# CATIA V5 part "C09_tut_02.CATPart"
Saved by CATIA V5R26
Part number: Part1
Bounding box of the stored display mesh (mm): x -258 to 0, y -74.587 to 74.587, z -81.796 to 81.796
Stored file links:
  D:\_Deepak\CATIA\CATIA V5 2015 Parts Files\Tutorial Files\Tutorials\c09_catia_v5_6r2015_tut\C09_tut_02.CATPart
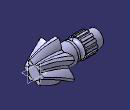
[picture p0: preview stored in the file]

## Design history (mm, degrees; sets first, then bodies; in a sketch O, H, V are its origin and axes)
Body1 (main body)
  Sketch1 on zx-plane, origin (0, 0, 0), H (-1, 0, 0), V (0, 0, 1)
    line L1 (0, 0) -> (258, 0)
    line L2 (258, 0) -> (258, -32.5)
    line L3 (0, 0) -> (0, -25)
    line L4 (0, -25) -> (95, -50)
    point P4 (95, -50)
    point P5 (95, -50)
    line L5 (95, -50) -> (95, -45)
    line L6 (95, -45) -> (100, -45)
    line L7 (100, -45) -> (100, -39)
    line L8 (100, -39) -> (146, -39)
    line L9 (258, -32.5) -> (226, -32.5)
    line L10 (226, -32.5) -> (226, -36)
    line L11 (226, -36) -> (178, -36)
    arc A1 centre (167, -36) radius 11 from (178, -36) to (156, -36) ccw
    point P13 (167, -36)
    line L12 (146, -39) -> (146, -38)
    line L13 (146, -38) -> (156, -38)
    line L14 (156, -38) -> (156, -36)
    point P16 (156, -36)
    point P17 (156, -36)
    axis line L15 (258, 0) -> (-34.5416, 0)
    length L1 = 258
    length L2 = 32.5
    length L3 = 25
    distance P4 L3 = 95
    length L5 = 5
    length L6 = 5
    distance L6 L1 = 45
    length L9 = 32
    length L10 = 3.5
    radius A1 = 11
    length L12 = 1
    length L13 = 10
    length L14 = 2
    distance L13 L1 = 38
    length L11 = 48
    horizontal: L1 H, L6 H, L8 H, L9 H, L11 H, L13 H, L15 H
    vertical: L2 V, L3 V, L5 V, L7 V, L10 V, L12 V, L14 V
    coincidence: P5 P4, P13 L11, P16 P17
  Shaft1: profile Sketch1, axis Sketch1.L15, angle 360
  Sketch2 on face of Shaft1 from Sketch1.L10, origin (-226, 0, 0), H (0, -1, 0), V (0, 0, 1)
    line L1 (-5, 40.6511) -> (5, 40.6511)
    line L2 (5, 40.6511) -> (5, 35.6511)
    line L3 (-5, 35.6511) -> (-5, 40.6511)
    point P3 (5, 35.6511)
    point P4 (-5, 35.6511)
    reference projected circle E1 centre (0, 0) radius 36 from edge [face of Shaft1 from Sketch1.L10 | face of Shaft1 from Sketch1.L11]
    reference projected circle E2 centre (0, 0) radius 36 from edge [face of Shaft1 from Sketch1.L10 | face of Shaft1 from Sketch1.L11]
    point P5 (0, 35.9986)
    point P6 (12.0414, 33.9264)
    arc A1 centre (0, 0) radius 36 from (5, 35.6511) to (-5, 35.6511) ccw
    length L3 = 5
    length L1 = 10
    distance L2 V = 5
    horizontal: L1 H
    vertical: L2 V, L3 V
    coincidence: P3 E1, P4 E2, P5 V
  Pad1: profile Sketch2, direction (1, 0, 0), length 48
  CircPattern1: of Pad1, instances 13, angular step 27.6923 {= 360.0*1 deg/CircPattern1.AngularNumber}, axis from face of Shaft1 from Sketch1.L9
  Plane1: type Offset, RefPlane face of Shaft1 from Sketch1.L2, Offset 163
  Sketch3 on Plane1, origin (-95, 0, 0), H (0, 1, 0), V (0, 0, 1)
    projected circle E1 centre (0, 0) radius 50 from edge [face of Shaft1 from Sketch1.L5 | face of Shaft1 from Sketch1.L4]
    projected arc E2 centre (0, 0) radius 50 from (20, 45.8258) to (-20, 45.8258) ccw from edge [face of Shaft1 from Sketch1.L5 | face of Shaft1 from Sketch1.L4]
    arc A1 centre (44.9551, 43.4104) radius 65 from (-20, 45.8258) to (-7.5, 81.7961) cw
    point P2 (-20, 45.8258)
    point P3 (-7.5, 81.7961)
    point P4 (20, 45.8258)
    point P5 (7.5, 81.7961)
    arc A2 centre (-44.9551, 43.4104) radius 65 from (20, 45.8258) to (7.5, 81.7961) ccw
    line L1 (-7.5, 81.7961) -> (7.5, 81.7961)
    radius A1 = 65
    length L1 = 15
    distance P2 P4 = 40
    coincidence: P2 E1
    symmetry: P2 P4 V, P3 P5 V, A1 A2 V
    horizontal: L1 H
  Plane2: type Offset, RefPlane face of Shaft1 from Sketch1.L2, Offset 210
  Sketch4 on Plane2, origin (-48, 0, 0), H (0, 1, 0), V (0, 0, 1)
    arc A1 centre (0, 0) radius 37.5 from (5.5935, 37.0805) to (-23.3843, 29.3159) ccw
    point P1 (5.5935, 37.0805)
    point P2 (-23.3843, 29.3159)
    arc A2 centre (-40.9945, 22.7216) radius 48.7506 from (5.5935, 37.0805) to (-10.4445, 60.7126) ccw
    point P3 (-10.4445, 60.7126)
    line L1 (-10.4445, 60.7126) -> (-21.3111, 57.8008)
    point P4 (-21.3111, 57.8008)
    arc A3 centre (24.1415, 40.1748) radius 48.7506 from (-21.3111, 57.8008) to (-23.3843, 29.3159) ccw
    reference projected circle E1 centre (0, 0) radius 25 from edge [face of Shaft1 from Sketch1.L4 | face of Shaft1 from Sketch1.L3]
    length L1 = 11.25
    radius A3 = 48.7506
    radius A1 = 37.5
    angle L1 H = 15
    radius A2 = 48.7506
    distance P1 V = 5.5935
    distance P2 V = 23.3843
    distance P3 V = 10.4445
    distance P4 H = 57.8008
    concentricity: A1 E1
  Sketch5 on face of Shaft1 from Sketch1.L3, origin (0, 0, 0), H (0, 1, 0), V (0, 0, 1)
    arc A1 centre (0, 0) radius 25 from (-2.7962, 24.8431) to (-20.1167, 14.8431) ccw
    arc A2 centre (-30.319, 7.5582) radius 32.5004 from (-2.7962, 24.8431) to (-17.2014, 37.2937) ccw
    line L1 (-17.2014, 37.2937) -> (-23.6966, 33.5437)
    arc A3 centre (8.6139, 30.0361) radius 32.5004 from (-23.6966, 33.5437) to (-20.1167, 14.8431) ccw
  Loft1: solid, Sections (Sketch3; Sketch4; Sketch5)
  CircPattern2: of Loft1, instances 6, angular step 60 {= 360.0*1 deg/CircPattern2.AngularNumber}, axis from face of Shaft1 from Sketch1.L4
